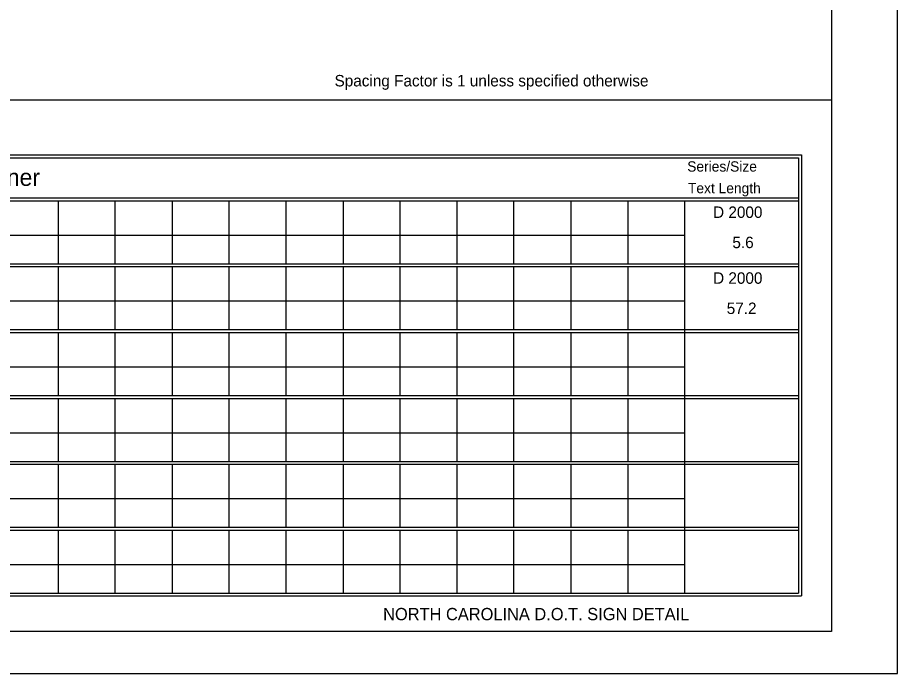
# Model space of a CAD drawing. Extents: x 1708.4 to 1771.6, y 238.3 to 283.4.
# Drawn here: x 1724.31 to 1738.43, y 262.4 to 272.92 of the extents above; entities that cross this region are included whole.
import ezdxf

# ---------------------------------------------------------------- set-up
doc = ezdxf.new("R2010")
doc.units = 0
doc.layers.add('Level 6', color=7, linetype='Continuous')
doc.layers.add('Level 9', color=7, linetype='Continuous')

msp = doc.modelspace()

# ---------------------------------------------------------------- linework, layer by layer
at = {"layer": 'Level 6'}
for p, q in [((1720.21, 271.603), (1737.374, 271.603)), ((1709.411, 270.031), (1731.189, 270.031)), ((1730.214, 270.031), (1736.846, 270.031)), ((1709.411, 269.985), (1731.189, 269.985)), ((1724.965, 269.985), (1724.965, 268.974)), ((1725.874, 269.985), (1725.874, 268.974)), ((1726.792, 269.985), (1726.792, 268.974)), ((1727.701, 269.985), (1727.701, 268.974)), ((1728.62, 269.985), (1728.62, 268.974)), ((1729.538, 269.985), (1729.538, 268.974)), ((1730.214, 269.985), (1736.846, 269.985)), ((1730.447, 269.985), (1730.447, 268.974)), ((1730.447, 269.985), (1730.447, 268.974)), ((1731.365, 269.985), (1731.365, 268.974)), ((1732.274, 269.985), (1732.274, 268.974)), ((1733.192, 269.985), (1733.192, 268.974)), ((1734.11, 269.985), (1734.11, 268.974)), ((1735.019, 269.985), (1735.019, 263.761)), ((1710.329, 269.433), (1731.189, 269.433)), ((1730.214, 269.433), (1735.019, 269.433)), ((1735.019, 269.224), (1735.019, 268.974)), ((1709.411, 268.974), (1731.189, 268.974)), ((1709.411, 268.928), (1731.189, 268.928)), ((1724.965, 268.928), (1724.965, 267.918)), ((1725.874, 268.928), (1725.874, 267.918)), ((1726.792, 268.928), (1726.792, 267.918)), ((1727.701, 268.928), (1727.701, 267.918)), ((1728.62, 268.928), (1728.62, 267.918)), ((1729.538, 268.928), (1729.538, 267.918)), ((1730.214, 268.974), (1736.846, 268.974)), ((1730.214, 268.928), (1736.846, 268.928)), ((1730.447, 268.928), (1730.447, 267.918)), ((1730.447, 268.928), (1730.447, 267.918)), ((1731.365, 268.928), (1731.365, 267.918)), ((1732.274, 268.928), (1732.274, 267.918)), ((1733.192, 268.928), (1733.192, 267.918)), ((1734.11, 268.928), (1734.11, 267.918)), ((1735.019, 268.928), (1735.019, 268.449)), ((1710.329, 268.377), (1731.189, 268.377)), ((1730.214, 268.377), (1735.019, 268.377)), ((1735.019, 268.247), (1735.019, 267.918)), ((1709.411, 267.918), (1731.189, 267.918)), ((1730.214, 267.918), (1736.846, 267.918)), ((1709.411, 267.872), (1731.189, 267.872)), ((1724.965, 267.872), (1724.965, 266.861)), ((1725.874, 267.872), (1725.874, 266.861)), ((1726.792, 267.872), (1726.792, 266.861)), ((1727.701, 267.872), (1727.701, 266.861)), ((1728.62, 267.872), (1728.62, 266.861)), ((1729.538, 267.872), (1729.538, 266.861)), ((1730.214, 267.872), (1736.846, 267.872)), ((1730.447, 267.872), (1730.447, 266.861)), ((1730.447, 267.872), (1730.447, 266.861)), ((1731.365, 267.872), (1731.365, 266.861)), ((1732.274, 267.872), (1732.274, 266.861)), ((1733.192, 267.872), (1733.192, 266.861)), ((1734.11, 267.872), (1734.11, 266.861)), ((1735.019, 267.872), (1735.019, 267.461)), ((1710.329, 267.321), (1731.189, 267.321)), ((1730.214, 267.321), (1735.019, 267.321)), ((1735.019, 267.159), (1735.019, 266.861)), ((1709.411, 266.861), (1731.189, 266.861)), ((1709.411, 266.815), (1731.189, 266.815)), ((1724.965, 266.815), (1724.965, 265.805)), ((1725.874, 266.815), (1725.874, 265.805)), ((1726.792, 266.815), (1726.792, 265.805)), ((1727.701, 266.815), (1727.701, 265.805)), ((1728.62, 266.815), (1728.62, 265.805)), ((1729.538, 266.815), (1729.538, 265.805)), ((1730.214, 266.861), (1736.846, 266.861)), ((1730.214, 266.815), (1736.846, 266.815)), ((1730.447, 266.815), (1730.447, 265.805)), ((1730.447, 266.815), (1730.447, 265.805)), ((1731.365, 266.815), (1731.365, 265.805)), ((1732.274, 266.815), (1732.274, 265.805)), ((1733.192, 266.815), (1733.192, 265.805)), ((1734.11, 266.815), (1734.11, 265.805)), ((1735.019, 266.815), (1735.019, 266.373)), ((1710.329, 266.264), (1731.189, 266.264)), ((1730.214, 266.264), (1735.019, 266.264)), ((1735.019, 266.07), (1735.019, 265.805)), ((1724.965, 265.922), (1724.965, 265.805)), ((1725.874, 265.922), (1725.874, 265.805)), ((1726.792, 265.922), (1726.792, 265.805)), ((1727.701, 265.922), (1727.701, 265.805)), ((1728.62, 265.922), (1728.62, 265.805)), ((1729.538, 265.922), (1729.538, 265.805)), ((1730.447, 265.922), (1730.447, 265.805)), ((1730.447, 265.922), (1730.447, 265.805)), ((1731.365, 265.922), (1731.365, 265.805)), ((1732.274, 265.922), (1732.274, 265.805)), ((1733.192, 265.922), (1733.192, 265.805)), ((1734.11, 265.922), (1734.11, 265.805)), ((1735.019, 265.922), (1735.019, 265.805)), ((1709.411, 265.805), (1731.189, 265.805)), ((1709.411, 265.805), (1731.189, 265.805)), ((1730.214, 265.805), (1736.846, 265.805)), ((1730.214, 265.805), (1736.846, 265.805)), ((1709.411, 265.759), (1731.189, 265.759)), ((1709.411, 265.759), (1731.189, 265.759)), ((1724.965, 265.759), (1724.965, 264.815)), ((1724.965, 265.759), (1724.965, 264.748)), ((1725.874, 265.759), (1725.874, 264.815)), ((1725.874, 265.759), (1725.874, 264.748)), ((1726.792, 265.759), (1726.792, 264.815)), ((1726.792, 265.759), (1726.792, 264.748)), ((1727.701, 265.759), (1727.701, 264.815)), ((1727.701, 265.759), (1727.701, 264.748)), ((1728.62, 265.759), (1728.62, 264.815)), ((1728.62, 265.759), (1728.62, 264.748)), ((1729.538, 265.759), (1729.538, 264.815)), ((1729.538, 265.759), (1729.538, 264.748)), ((1730.214, 265.759), (1736.846, 265.759)), ((1730.214, 265.759), (1736.846, 265.759)), ((1730.447, 265.759), (1730.447, 264.815)), ((1730.447, 265.759), (1730.447, 264.748)), ((1730.447, 265.759), (1730.447, 264.815)), ((1730.447, 265.759), (1730.447, 264.748)), ((1731.365, 265.759), (1731.365, 264.815)), ((1731.365, 265.759), (1731.365, 264.748)), ((1732.274, 265.759), (1732.274, 264.815)), ((1732.274, 265.759), (1732.274, 264.748)), ((1733.192, 265.759), (1733.192, 264.815)), ((1733.192, 265.759), (1733.192, 264.748)), ((1734.11, 265.759), (1734.11, 264.815)), ((1734.11, 265.759), (1734.11, 264.748)), ((1735.019, 265.759), (1735.019, 265.304)), ((1735.019, 265.759), (1735.019, 265.304)), ((1710.329, 265.208), (1731.189, 265.208)), ((1710.329, 265.208), (1731.189, 265.208)), ((1730.214, 265.208), (1735.019, 265.208)), ((1730.214, 265.208), (1734.781, 265.208)), ((1735.019, 265.042), (1735.019, 264.815)), ((1735.019, 265.042), (1735.019, 264.748)), ((1724.965, 264.866), (1724.965, 264.748)), ((1725.874, 264.866), (1725.874, 264.748)), ((1726.792, 264.866), (1726.792, 264.748)), ((1727.701, 264.866), (1727.701, 264.748)), ((1728.62, 264.866), (1728.62, 264.748)), ((1729.538, 264.866), (1729.538, 264.748)), ((1730.447, 264.866), (1730.447, 264.748)), ((1730.447, 264.866), (1730.447, 264.748)), ((1731.365, 264.866), (1731.365, 264.748)), ((1732.274, 264.866), (1732.274, 264.748)), ((1733.192, 264.866), (1733.192, 264.748)), ((1734.11, 264.866), (1734.11, 264.748)), ((1735.019, 264.866), (1735.019, 264.748)), ((1709.411, 264.748), (1731.189, 264.748)), ((1709.411, 264.748), (1731.189, 264.748)), ((1709.411, 264.702), (1731.189, 264.702)), ((1709.411, 264.702), (1731.189, 264.702)), ((1724.965, 264.702), (1724.965, 263.692)), ((1724.965, 264.702), (1724.965, 263.692)), ((1725.874, 264.702), (1725.874, 263.692)), ((1725.874, 264.702), (1725.874, 263.692)), ((1726.792, 264.702), (1726.792, 263.692)), ((1726.792, 264.702), (1726.792, 263.692)), ((1727.701, 264.702), (1727.701, 263.692)), ((1727.701, 264.702), (1727.701, 263.692)), ((1728.62, 264.702), (1728.62, 263.692)), ((1728.62, 264.702), (1728.62, 263.692)), ((1729.538, 264.702), (1729.538, 263.692)), ((1729.538, 264.702), (1729.538, 263.692)), ((1730.214, 264.748), (1736.846, 264.748)), ((1730.214, 264.748), (1736.846, 264.748)), ((1730.214, 264.702), (1736.846, 264.702)), ((1730.214, 264.702), (1736.846, 264.702)), ((1730.447, 264.702), (1730.447, 263.692)), ((1730.447, 264.702), (1730.447, 263.692)), ((1730.447, 264.702), (1730.447, 263.692)), ((1730.447, 264.702), (1730.447, 263.692)), ((1731.365, 264.702), (1731.365, 263.692)), ((1731.365, 264.702), (1731.365, 263.692)), ((1732.274, 264.702), (1732.274, 263.692)), ((1732.274, 264.702), (1732.274, 263.692)), ((1733.192, 264.702), (1733.192, 263.692)), ((1733.192, 264.702), (1733.192, 263.692)), ((1734.11, 264.702), (1734.11, 263.692)), ((1734.11, 264.702), (1734.11, 263.692)), ((1735.019, 264.702), (1735.019, 264.277)), ((1735.019, 264.702), (1735.019, 264.277)), ((1710.329, 264.151), (1731.189, 264.151)), ((1710.329, 264.151), (1731.189, 264.151)), ((1730.214, 264.151), (1735.019, 264.151)), ((1730.214, 264.151), (1734.843, 264.151)), ((1735.019, 263.955), (1735.019, 263.692)), ((1735.019, 263.955), (1735.019, 263.692)), ((1709.364, 263.646), (1731.189, 263.646)), ((1709.411, 263.692), (1731.189, 263.692)), ((1709.411, 263.692), (1731.189, 263.692)), ((1709.411, 263.646), (1731.189, 263.646)), ((1730.214, 263.692), (1736.846, 263.692)), ((1730.214, 263.692), (1736.846, 263.692)), ((1730.214, 263.646), (1736.893, 263.646)), ((1730.214, 263.646), (1736.846, 263.646))]:
    msp.add_line(p, q, dxfattribs=at)
msp.add_lwpolyline([(1709.048, 282.744), (1737.374, 282.744), (1737.374, 263.077), (1709.048, 263.077)], close=True, dxfattribs=at)
for points in [[(1709.364, 264.815), (1709.364, 270.72), (1731.189, 270.72)], [(1730.214, 270.72), (1736.893, 270.72), (1736.893, 264.815)], [(1709.411, 264.815), (1709.411, 270.674), (1731.189, 270.674)], [(1730.214, 270.674), (1736.846, 270.674), (1736.846, 264.815)], [(1736.846, 265.922), (1736.846, 263.692)], [(1736.893, 265.922), (1736.893, 263.646)]]:
    msp.add_lwpolyline(points, dxfattribs=at)
at = {"layer": 'Level 9'}
msp.add_lwpolyline([(1708.357, 262.404), (1738.434, 262.404), (1738.434, 283.439), (1708.357, 283.439)], close=True, dxfattribs=at)

# ---------------------------------------------------------------- texts
at = {"layer": 'Level 6'}
for s, height, p in [('Spacing Factor is 1 unless specified otherwise', 0.18373, (1729.4, 271.818)), ('Series/Size', 0.16535, (1735.061, 270.452)), ('Letter locations are panel edge to lower left corner', 0.27559, (1716.478, 270.222)), ('Text Length', 0.16535, (1735.073, 270.104)), ('NORTH CAROLINA D.O.T. SIGN DETAIL', 0.19685, (1730.18, 263.257))]:
    msp.add_text(s, height=height, rotation=360, dxfattribs=at).set_placement(p)
for s, p in [('D 2000', (1735.476, 269.709)), ('5.6', (1735.786, 269.224)), ('D 2000', (1735.476, 268.653)), ('57.2', (1735.695, 268.168))]:
    msp.add_text(s, height=0.1837, dxfattribs=at).set_placement(p)

doc.saveas('drawing.dxf')
